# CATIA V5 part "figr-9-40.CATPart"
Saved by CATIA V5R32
Part number: Part1
Bounding box of the stored display mesh (mm): x -40 to 40, y -20 to 191.034, z 0 to 131.919
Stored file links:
  D:\PROJECTS\Project 2022\CATIA V5 6R 2022\Resources\Part Files\c09_catia_v5_6r2022_prt\c09_catia_v5_6r2022_prt\figr-9-40.CATPart
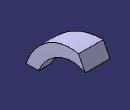
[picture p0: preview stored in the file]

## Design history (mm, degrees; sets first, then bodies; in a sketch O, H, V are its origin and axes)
Set1
  Plane1: type Normal, Curve Sketch2, RefPoint vertex of Sketch2
Body1 (main body)
  Sketch1 on xy-plane, origin (0, 0, 0), H (1, 0, 0), V (0, 1, 0)
    line L1 (20, 20) -> (20, -20)
    line L2 (20, -20) -> (-20, -20)
    line L3 (-20, -20) -> (-20, 20)
    line L4 (-20, 20) -> (20, 20)
    vertical: L1 V, L3 V
    horizontal: L2 H, L4 H
    equidistance: L1 L3 O, L2 L4 O
  Sketch2 on yz-plane, origin (0, 0, 0), H (0, 1, 0), V (0, 0, 1)
    spline S1 through (0, 0) (20, 60) (60, 80) (120, 90) (180, 110)
    point P1 (0, 0)
    coincidence: P1 O
  Sketch3 on Plane1, origin (0, 186.3865, 97.8327), H (1, 0, 0), V (0, -0.4648, 0.8854)
    point P1 (0, 13.7415)
    line L1 (40, 37.4831) -> (40, -10)
    line L2 (40, -10) -> (-40, -10)
    line L3 (-40, -10) -> (-40, 37.4831)
    line L4 (-40, 37.4831) -> (40, 37.4831)
    reference projected point E1 (0, 13.7415) from vertex of Sketch2
    coincidence: P1 V, P1 E1
    vertical: L1 V, L3 V
    horizontal: L2 H, L4 H
    equidistance: L1 L3 P1, L2 L4 P1
  Loft1: Sections (Sketch1; Sketch3)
